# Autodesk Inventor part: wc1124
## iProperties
Shininess: 64.0
Length Units: 11272
Angle Units: 11279
Time Units: 11290
Mass Units: 11286
Length Display Precision: 3
Angle Display Precision: 2
Compacted: True
Part Number: wc1124
Document SubType Name: Modeling
Created: 2004-08
Designer: John Blackburn
Manufacturer: Standard
Standards Organization: Custom
Material: Delrin, Black
Density: 0.0
Volumn: 0.0
Area: 0.0
PropertySet Name: Model Information
Control State: 0
Master: False
Checked Out: False
Author: John Blackburn
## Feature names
1. Base1
